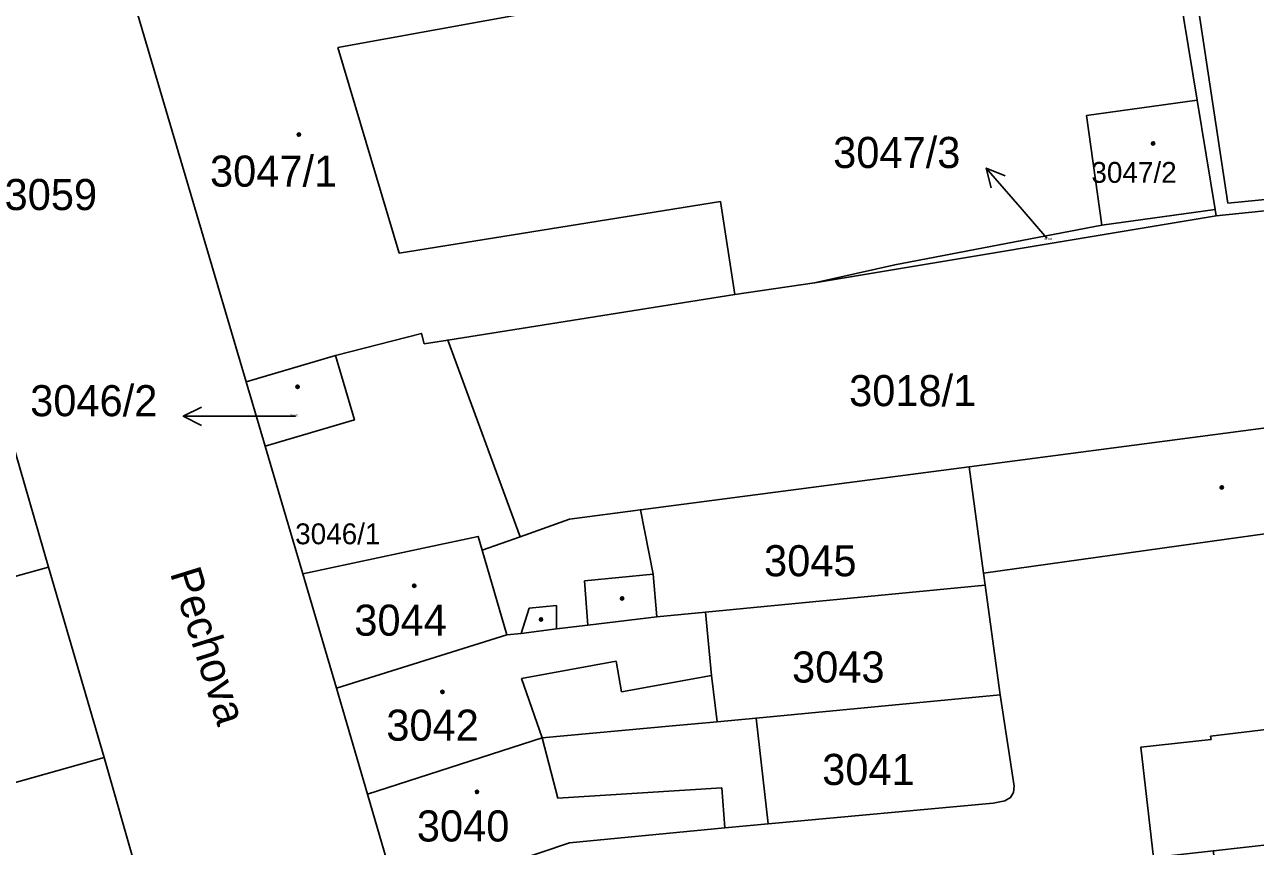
# Model space of a CAD drawing. Extents: x -596233 to -595156, y -1161235 to -1159375.
# Drawn here: x -595507.7 to -595440.4, y -1160838.7 to -1160793.7 of the extents above; entities that cross this region are included whole.
import ezdxf

# ---------------------------------------------------------------- set-up
doc = ezdxf.new("R2010")
doc.units = 0
for name, color, linetype in [('KN_CAR_KR', 7, 'Continuous'), ('KN_KULTURY', 7, 'Continuous'), ('KN_PARC_CIS_POM', 7, 'Continuous'), ('KN_PARC_CIS_POZ', 7, 'Continuous'), ('KN_PARC_CIS_STAV', 7, 'Continuous'), ('KN_PARC_PLOCHA', 7, 'Continuous'), ('KN_ULICE', 7, 'Continuous'), ('PARC_C_SIPKA', 7, 'Continuous'), ('parcely_l', 7, 'Continuous')]:
    doc.layers.add(name, color=color, linetype=linetype)

msp = doc.modelspace()

# ---------------------------------------------------------------- linework, layer by layer
at = {"layer": 'KN_CAR_KR'}
for points in [[(-595445.16, -1160782.15), (-595441.93, -1160803.49)], [(-595471.79, -1160791.56), (-595490.59, -1160794.98)], [(-595490.59, -1160794.98), (-595487.23, -1160806.22)], [(-595441.93, -1160803.49), (-595436.9, -1160803)], [(-595487.23, -1160806.22), (-595469.67, -1160803.4)], [(-595469.67, -1160803.4), (-595468.89, -1160808.48)], [(-595429.43, -1160820.12), (-595442, -1160821.87)], [(-595455.28, -1160823.72), (-595442, -1160821.87)], [(-595482.69, -1160822.47), (-595481.35, -1160827.1)], [(-595473.34, -1160823.77), (-595477.11, -1160824.14)], [(-595477.11, -1160824.14), (-595476.92, -1160826.56)], [(-595480.57, -1160827.01), (-595480.12, -1160825.64)], [(-595480.12, -1160825.64), (-595478.64, -1160825.49)], [(-595478.64, -1160825.49), (-595478.64, -1160826.77)], [(-595480.54, -1160829.48), (-595475.38, -1160828.54)], [(-595475.38, -1160828.54), (-595475.08, -1160830.2)], [(-595475.08, -1160830.2), (-595470.16, -1160829.31)], [(-595480.54, -1160829.48), (-595479.42, -1160832.73)], [(-595479.42, -1160832.73), (-595478.56, -1160836.03)], [(-595478.56, -1160836.03), (-595469.59, -1160835.46)], [(-595469.43, -1160837.65), (-595469.59, -1160835.46)]]:
    msp.add_lwpolyline(points, dxfattribs=at)
at = {"layer": 'KN_KULTURY'}
for centre, radius in [((-595492.72, -1160799.74), 0.09), ((-595492.72, -1160799.74), 0.0398), ((-595446.02, -1160800.23), 0.09), ((-595446.02, -1160800.23), 0.0398), ((-595492.79, -1160813.53), 0.09), ((-595492.79, -1160813.53), 0.0398), ((-595442.26, -1160819.03), 0.09), ((-595442.26, -1160819.03), 0.0398), ((-595486.41, -1160824.41), 0.09), ((-595486.41, -1160824.41), 0.0398), ((-595475.05, -1160825.1), 0.09), ((-595475.05, -1160825.1), 0.0398), ((-595479.48, -1160826.25), 0.09), ((-595479.48, -1160826.25), 0.0398), ((-595484.87, -1160830.21), 0.09), ((-595484.87, -1160830.21), 0.0398), ((-595482.98, -1160835.68), 0.09), ((-595482.98, -1160835.68), 0.0398)]:
    msp.add_circle(centre, radius, dxfattribs=at)
at = {"layer": 'KN_PARC_PLOCHA'}
for points in [[(-595397.67, -1160797.36), (-595398.23, -1160797.29), (-595402.38, -1160796.75), (-595413.49, -1160799.95), (-595414.98, -1160800.44), (-595422.6, -1160801.54), (-595431.73, -1160803.03), (-595432.68, -1160803.18), (-595436.9, -1160803.61), (-595442.56, -1160804.19), (-595442.62, -1160803.83), (-595443.6, -1160797.86), (-595446.26, -1160781.68), (-595442.23, -1160780.95), (-595440.69, -1160780.67), (-595432.23, -1160779.14), (-595426.55, -1160778.34), (-595409.61, -1160775.41), (-595403.16, -1160774.3), (-595398.41, -1160773.48), (-595398.4, -1160773.7), (-595397.97, -1160787.78)], [(-595443.6, -1160797.86), (-595449.65, -1160798.7), (-595448.82, -1160804.69), (-595460.14, -1160806.86), (-595464.52, -1160807.85), (-595468.89, -1160808.48), (-595484.58, -1160810.98), (-595485.86, -1160811.18), (-595486.02, -1160810.61), (-595490.72, -1160811.82), (-595495.6, -1160813.26), (-595501.75, -1160792.39), (-595492.06, -1160789.56), (-595491.96, -1160790.12), (-595487.2, -1160789.23), (-595482.56, -1160788.35), (-595467.3, -1160785.53), (-595462.84, -1160784.68), (-595446.26, -1160781.68)], [(-595442.62, -1160803.83), (-595448.82, -1160804.69), (-595449.65, -1160798.7), (-595443.6, -1160797.86)], [(-595430.22, -1160814.45), (-595435, -1160815.13), (-595442.75, -1160816.15), (-595456.07, -1160817.9), (-595474.05, -1160820.25), (-595477.92, -1160820.76), (-595480.62, -1160821.73), (-595484.58, -1160810.98), (-595468.89, -1160808.48), (-595464.52, -1160807.85), (-595442.56, -1160804.19), (-595436.9, -1160803.61), (-595432.68, -1160803.18), (-595431.73, -1160803.03)], [(-595442.56, -1160804.19), (-595464.52, -1160807.85), (-595460.14, -1160806.86), (-595448.82, -1160804.69), (-595442.62, -1160803.83)], [(-595484.58, -1160810.98), (-595480.62, -1160821.73), (-595482.69, -1160822.47), (-595482.91, -1160821.71), (-595485.66, -1160822.3), (-595492.5, -1160823.76), (-595493.55, -1160820.19), (-595494.56, -1160816.78), (-595489.68, -1160815.34), (-595490.72, -1160811.82), (-595486.02, -1160810.61), (-595485.86, -1160811.18)], [(-595494.56, -1160816.78), (-595495.6, -1160813.26), (-595490.72, -1160811.82), (-595489.68, -1160815.34)], [(-595506.4, -1160823.4), (-595516.61, -1160826.21), (-595516.63, -1160826.13), (-595521.89, -1160826.97), (-595524.75, -1160817.06), (-595521.42, -1160816.62), (-595521.37, -1160816.62), (-595519.54, -1160816.34), (-595509.29, -1160813.47)], [(-595455.19, -1160824.38), (-595470.49, -1160825.85), (-595473.15, -1160826.1), (-595473.34, -1160823.77), (-595474.05, -1160820.25), (-595456.07, -1160817.9), (-595455.28, -1160823.72)], [(-595473.15, -1160826.1), (-595476.92, -1160826.56), (-595478.64, -1160826.77), (-595480.57, -1160827.01), (-595481.35, -1160827.1), (-595490.67, -1160830), (-595492.5, -1160823.76), (-595485.66, -1160822.3), (-595482.91, -1160821.71), (-595482.69, -1160822.47), (-595480.62, -1160821.73), (-595477.92, -1160820.76), (-595474.05, -1160820.25), (-595473.34, -1160823.77)], [(-595503.37, -1160833.79), (-595513.03, -1160836.51), (-595516.7, -1160837.52), (-595518.32, -1160831.24), (-595520.91, -1160831.93), (-595521.89, -1160826.97), (-595516.63, -1160826.13), (-595516.61, -1160826.21), (-595506.4, -1160823.4)], [(-595454.37, -1160830.37), (-595467.72, -1160831.64), (-595469.85, -1160831.84), (-595470.16, -1160829.31), (-595470.49, -1160825.85), (-595455.19, -1160824.38)], [(-595469.85, -1160831.84), (-595472.3, -1160832.07), (-595479.42, -1160832.73), (-595488.97, -1160835.8), (-595490.67, -1160830), (-595481.35, -1160827.1), (-595480.57, -1160827.01), (-595478.64, -1160826.77), (-595476.92, -1160826.56), (-595473.15, -1160826.1), (-595470.49, -1160825.85), (-595470.16, -1160829.31)], [(-595406.52, -1160833.2), (-595408.21, -1160834.96), (-595411.73, -1160835.4), (-595419, -1160836.24), (-595421.5, -1160836.52), (-595422.41, -1160836.62), (-595428.11, -1160837.26), (-595442.72, -1160838.9), (-595446, -1160839.27), (-595446.68, -1160833.23), (-595442.85, -1160832.81), (-595442.87, -1160832.64), (-595431.79, -1160831.3), (-595424.4, -1160830.49), (-595424.36, -1160830.86), (-595418.41, -1160830.21), (-595418.54, -1160828.32), (-595416.52, -1160828.24), (-595416.57, -1160825.64), (-595407.8, -1160826.22), (-595407.16, -1160832.67), (-595406.58, -1160832.58), (-595406.67, -1160833.18)], [(-595467.06, -1160837.43), (-595467.72, -1160831.64), (-595454.37, -1160830.37), (-595453.62, -1160835.37), (-595453.64, -1160835.71), (-595453.81, -1160835.99), (-595454.13, -1160836.17), (-595454.76, -1160836.29)], [(-595467.06, -1160837.43), (-595469.43, -1160837.65), (-595477.92, -1160838.46), (-595487.27, -1160841.61), (-595488.97, -1160835.8), (-595479.42, -1160832.73), (-595472.3, -1160832.07), (-595469.85, -1160831.84), (-595467.72, -1160831.64)], [(-595501.67, -1160839.74), (-595519.78, -1160844.68), (-595528.27, -1160845.31), (-595528.33, -1160844.66), (-595531.84, -1160844.98), (-595532.18, -1160841.39), (-595532.3, -1160839.58), (-595520.65, -1160838.61), (-595516.7, -1160837.52), (-595513.03, -1160836.51), (-595503.37, -1160833.79)], [(-595427.96, -1160850.45), (-595434.07, -1160850.79), (-595439.84, -1160851.45), (-595442.03, -1160851.7), (-595442.37, -1160845.41), (-595442.72, -1160838.9), (-595428.11, -1160837.26), (-595427.88, -1160839.96), (-595428.18, -1160846.58)]]:
    msp.add_lwpolyline(points, close=True, dxfattribs=at)
for points in [[(-595501.75, -1160792.39), (-595495.6, -1160813.26), (-595494.56, -1160816.78), (-595493.55, -1160820.19), (-595492.5, -1160823.76), (-595490.67, -1160830), (-595488.97, -1160835.8), (-595487.27, -1160841.61), (-595486.21, -1160845.2), (-595484.45, -1160851.26), (-595482.69, -1160857.3), (-595476.84, -1160877.42), (-595493.24, -1160877.7), (-595491.31, -1160875.01), (-595492.59, -1160870.61), (-595492.65, -1160870.63), (-595497.09, -1160855.27), (-595497.22, -1160855.31), (-595500.55, -1160843.68), (-595501.67, -1160839.74), (-595503.37, -1160833.79), (-595506.4, -1160823.4), (-595509.29, -1160813.47)], [(-595431.79, -1160831.3), (-595442.87, -1160832.64), (-595442.85, -1160832.81), (-595446.68, -1160833.23), (-595446, -1160839.27), (-595462.47, -1160840.71), (-595465.99, -1160841.03), (-595476.76, -1160842.02), (-595486.21, -1160845.2), (-595487.27, -1160841.61), (-595477.92, -1160838.46), (-595469.43, -1160837.65), (-595467.06, -1160837.43), (-595454.76, -1160836.29), (-595454.13, -1160836.17), (-595453.81, -1160835.99), (-595453.64, -1160835.71), (-595453.62, -1160835.37), (-595454.37, -1160830.37), (-595455.19, -1160824.38), (-595455.28, -1160823.72), (-595456.07, -1160817.9), (-595442.75, -1160816.15), (-595435, -1160815.13)]]:
    msp.add_lwpolyline(points, dxfattribs=at)
at = {"layer": 'PARC_C_SIPKA'}
for points in [[(-595454.8661, -1160802.6537), (-595455.1416, -1160801.5702), (-595454.1095, -1160801.9999)], [(-595451.83, -1160805.4), (-595453.18, -1160803.84), (-595455.1416, -1160801.5702)], [(-595498.04, -1160815.64), (-595499.04, -1160815.14), (-595498.04, -1160814.64)], [(-595492.91, -1160815.14), (-595496.04, -1160815.14), (-595499.04, -1160815.14)]]:
    msp.add_lwpolyline(points, dxfattribs=at)
at = {"layer": 'parcely_l'}
for points in [[(-595446.26, -1160781.68), (-595443.6, -1160797.86)], [(-595501.75, -1160792.39), (-595495.6, -1160813.26)], [(-595448.82, -1160804.69), (-595449.65, -1160798.7), (-595443.6, -1160797.86)], [(-595443.6, -1160797.86), (-595442.62, -1160803.83)], [(-595442.56, -1160804.19), (-595436.9, -1160803.61), (-595432.68, -1160803.18), (-595431.73, -1160803.03)], [(-595442.56, -1160804.19), (-595464.52, -1160807.85)], [(-595442.62, -1160803.83), (-595448.82, -1160804.69)], [(-595442.62, -1160803.83), (-595442.56, -1160804.19)], [(-595464.52, -1160807.85), (-595460.14, -1160806.86), (-595448.82, -1160804.69)], [(-595464.52, -1160807.85), (-595468.89, -1160808.48), (-595484.58, -1160810.98)], [(-595484.58, -1160810.98), (-595485.86, -1160811.18), (-595486.02, -1160810.61), (-595490.72, -1160811.82)], [(-595484.58, -1160810.98), (-595480.62, -1160821.73)], [(-595490.72, -1160811.82), (-595495.6, -1160813.26)], [(-595494.56, -1160816.78), (-595489.68, -1160815.34), (-595490.72, -1160811.82)], [(-595506.4, -1160823.4), (-595509.29, -1160813.47)], [(-595495.6, -1160813.26), (-595494.56, -1160816.78)], [(-595430.22, -1160814.45), (-595435, -1160815.13), (-595442.75, -1160816.15), (-595456.07, -1160817.9)], [(-595494.56, -1160816.78), (-595493.55, -1160820.19), (-595492.5, -1160823.76)], [(-595456.07, -1160817.9), (-595474.05, -1160820.25)], [(-595455.19, -1160824.38), (-595455.28, -1160823.72), (-595456.07, -1160817.9)], [(-595474.05, -1160820.25), (-595477.92, -1160820.76), (-595480.62, -1160821.73)], [(-595474.05, -1160820.25), (-595473.34, -1160823.77), (-595473.15, -1160826.1)], [(-595480.62, -1160821.73), (-595482.69, -1160822.47), (-595482.91, -1160821.71), (-595485.66, -1160822.3), (-595492.5, -1160823.76)], [(-595506.4, -1160823.4), (-595516.61, -1160826.21), (-595516.63, -1160826.13), (-595521.89, -1160826.97)], [(-595503.37, -1160833.79), (-595506.4, -1160823.4)], [(-595492.5, -1160823.76), (-595490.67, -1160830)], [(-595470.49, -1160825.85), (-595455.19, -1160824.38)], [(-595455.19, -1160824.38), (-595454.37, -1160830.37)], [(-595473.15, -1160826.1), (-595470.49, -1160825.85)], [(-595469.85, -1160831.84), (-595470.16, -1160829.31), (-595470.49, -1160825.85)], [(-595406.52, -1160833.2), (-595406.67, -1160833.18), (-595406.58, -1160832.58), (-595407.16, -1160832.67), (-595407.8, -1160826.22), (-595416.57, -1160825.64), (-595416.52, -1160828.24), (-595418.54, -1160828.32), (-595418.41, -1160830.21), (-595424.36, -1160830.86), (-595424.4, -1160830.49), (-595431.79, -1160831.3), (-595442.87, -1160832.64), (-595442.85, -1160832.81), (-595446.68, -1160833.23), (-595446, -1160839.27)], [(-595473.15, -1160826.1), (-595476.92, -1160826.56), (-595478.64, -1160826.77), (-595480.57, -1160827.01), (-595481.35, -1160827.1), (-595490.67, -1160830)], [(-595490.67, -1160830), (-595488.97, -1160835.8)], [(-595454.37, -1160830.37), (-595467.72, -1160831.64)], [(-595454.37, -1160830.37), (-595453.62, -1160835.37), (-595453.64, -1160835.71), (-595453.81, -1160835.99), (-595454.13, -1160836.17), (-595454.76, -1160836.29), (-595467.06, -1160837.43)], [(-595488.97, -1160835.8), (-595479.42, -1160832.73), (-595472.3, -1160832.07), (-595469.85, -1160831.84)], [(-595467.72, -1160831.64), (-595469.85, -1160831.84)], [(-595467.06, -1160837.43), (-595467.72, -1160831.64)], [(-595503.37, -1160833.79), (-595513.03, -1160836.51), (-595516.7, -1160837.52)], [(-595501.67, -1160839.74), (-595503.37, -1160833.79)], [(-595488.97, -1160835.8), (-595487.27, -1160841.61)], [(-595442.72, -1160838.9), (-595428.11, -1160837.26)], [(-595487.27, -1160841.61), (-595477.92, -1160838.46), (-595469.43, -1160837.65), (-595467.06, -1160837.43)]]:
    msp.add_lwpolyline(points, dxfattribs=at)

# ---------------------------------------------------------------- texts
at = {"layer": 'KN_PARC_CIS_POM'}
for s, p in [('3047/3', (-595451.9633, -1160805.5)), ('3046/2', (-595493.1933, -1160815.14))]:
    msp.add_text(s, height=0.1, dxfattribs=at).set_placement(p)
at = {"layer": 'KN_PARC_CIS_POZ'}
for s, height, p in [('3047/3', 1.7, (-595463.5066, -1160801.57)), ('3059', 1.7, (-595508.8066, -1160803.87)), ('3018/1', 1.7, (-595462.6366, -1160814.59)), ('3046/1', 1.14, (-595492.92, -1160822.14)), ('3045', 1.7, (-595467.2866, -1160823.89)), ('3043', 1.7, (-595465.7566, -1160829.7)), ('3041', 1.7, (-595464.1066, -1160835.3))]:
    msp.add_text(s, height=height, dxfattribs=at).set_placement(p)
at = {"layer": 'KN_PARC_CIS_STAV'}
for s, height, p in [('3047/1', 1.7, (-595497.5766, -1160802.59)), ('3047/2', 1.14, (-595449.39, -1160802.38)), ('3046/2', 1.7, (-595507.4066, -1160815.14)), ('3044', 1.7, (-595489.6866, -1160827.14)), ('3042', 1.7, (-595487.9366, -1160832.88)), ('3040', 1.7, (-595486.2666, -1160838.39))]:
    msp.add_text(s, height=height, dxfattribs=at).set_placement(p)
at = {"layer": 'KN_ULICE'}
msp.add_text('Pechova', height=1.7, rotation=287.32829, dxfattribs=at).set_placement((-595499.7778, -1160823.7106))

doc.saveas('drawing.dxf')
